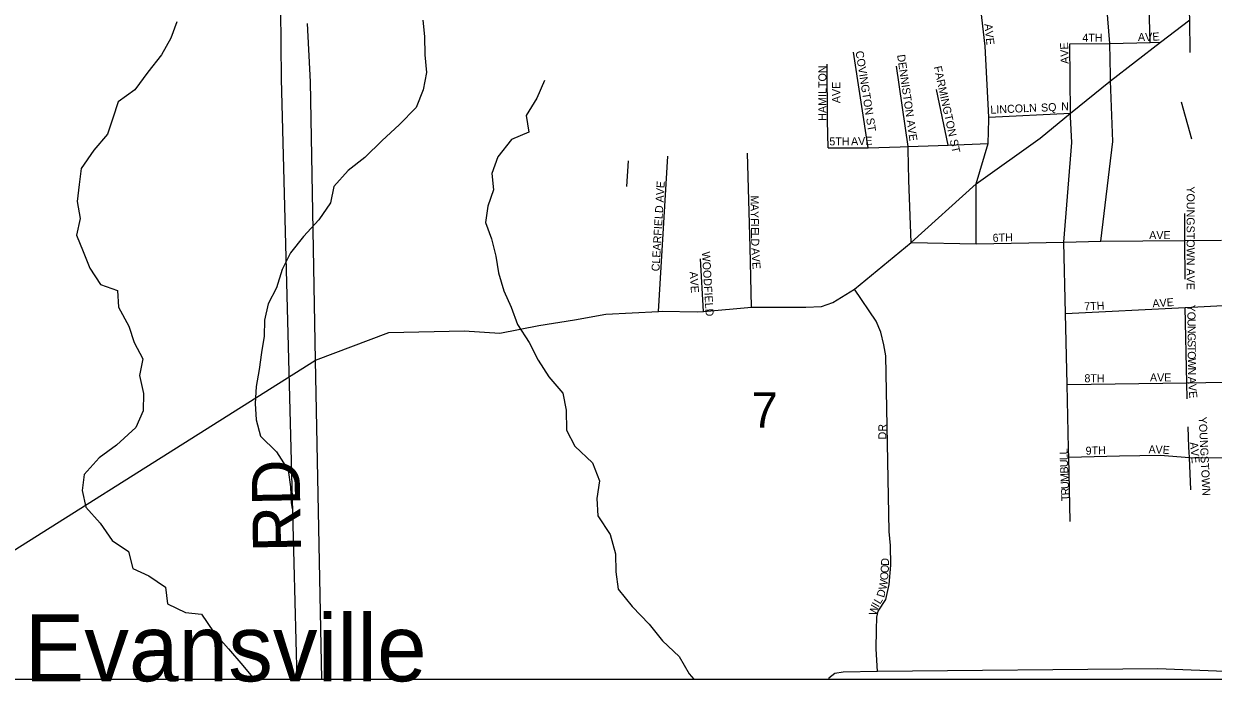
# Model space of a CAD drawing. Extents: x -37878.7 to -37844.7, y -19791.4 to -19769.4.
# Drawn here: x -37872.428 to -37871.021, y -19777.389 to -19776.611 of the extents above; entities that cross this region are included whole.
import ezdxf

# ---------------------------------------------------------------- set-up
doc = ezdxf.new("R2010")
doc.units = 0
for name, color, linetype in [('GM_X_County_Road', 7, 'Continuous'), ('GM_X_Minor_River', 7, 'Continuous'), ('GM_X_Section', 7, 'Continuous'), ('GM_X_Section_Text', 7, 'Continuous'), ('GM_X_Township_Road', 7, 'Continuous'), ('GM_X_Township_Road_Text', 7, 'Continuous'), ('GM_X_Township_Subdivision', 7, 'Continuous'), ('GM_X_Township_Subdivision_Text', 7, 'Continuous'), ('GM_X_Unincorporated_Text', 7, 'Continuous'), ('SH_Data', 7, 'Continuous')]:
    doc.layers.add(name, color=color, linetype=linetype)

msp = doc.modelspace()

# ---------------------------------------------------------------- linework, layer by layer
at = {"layer": 'GM_X_County_Road'}
for points in [[(-37872.0827, -19777.0084), (-37871.996, -19776.9759), (-37871.9068, -19776.974), (-37871.8646, -19776.9764), (-37871.8185, -19776.9676), (-37871.7765, -19776.9609), (-37871.7394, -19776.9542), (-37871.7083, -19776.9527), (-37871.6771, -19776.9509), (-37871.6726, -19776.9506), (-37871.6312, -19776.9515), (-37871.624, -19776.9511), (-37871.5669, -19776.9457), (-37871.5029, -19776.9457), (-37871.4842, -19776.9449), (-37871.471, -19776.9403), (-37871.4452, -19776.9247), (-37871.3781, -19776.8692), (-37871.3015, -19776.8), (-37871.2255, -19776.7462), (-37871.1899, -19776.7165), (-37871.1423, -19776.6783), (-37871.0832, -19776.6324), (-37871.0487, -19776.6062)], [(-37872.6858, -19777.3854), (-37872.5796, -19777.3214), (-37872.0827, -19777.0084)]]:
    msp.add_lwpolyline(points, dxfattribs=at)
at = {"layer": 'GM_X_Minor_River'}
for points in [[(-37872.2467, -19776.6084), (-37872.2539, -19776.6279), (-37872.2649, -19776.6475), (-37872.2811, -19776.668), (-37872.2966, -19776.6888), (-37872.3163, -19776.7033), (-37872.3224, -19776.7224), (-37872.3288, -19776.7415), (-37872.3451, -19776.7604), (-37872.3598, -19776.782), (-37872.3624, -19776.801), (-37872.3647, -19776.8208), (-37872.3612, -19776.8409), (-37872.3653, -19776.8607), (-37872.3574, -19776.8799), (-37872.3498, -19776.8998), (-37872.3369, -19776.9189), (-37872.317, -19776.9261), (-37872.3158, -19776.9458), (-37872.3036, -19776.9683), (-37872.2972, -19776.9875), (-37872.2869, -19777.007), (-37872.2911, -19777.0265), (-37872.2861, -19777.048), (-37872.2864, -19777.0685), (-37872.2951, -19777.0881), (-37872.3181, -19777.1091), (-37872.3387, -19777.1239), (-37872.3564, -19777.1437), (-37872.3587, -19777.1627), (-37872.3545, -19777.1823), (-37872.3374, -19777.2013), (-37872.3234, -19777.2215), (-37872.3038, -19777.2348), (-37872.2988, -19777.2548), (-37872.2797, -19777.2635), (-37872.2601, -19777.2767), (-37872.2578, -19777.2964), (-37872.2367, -19777.3066), (-37872.2174, -19777.3089), (-37872.2033, -19777.3298), (-37872.1855, -19777.3499), (-37872.1688, -19777.3693), (-37872.1553, -19777.3854)], [(-37871.9558, -19776.6064), (-37871.9539, -19776.6257), (-37871.9534, -19776.6477), (-37871.9515, -19776.6685), (-37871.9556, -19776.6891), (-37871.9635, -19776.7098), (-37871.9839, -19776.7303), (-37872.004, -19776.749), (-37872.0244, -19776.7688), (-37872.0442, -19776.7844), (-37872.0612, -19776.8033), (-37872.065, -19776.8224), (-37872.079, -19776.8424), (-37872.0971, -19776.8622), (-37872.1122, -19776.8815), (-37872.122, -19776.9014), (-37872.1288, -19776.9228), (-37872.1386, -19776.942), (-37872.1432, -19776.9611), (-37872.1435, -19776.9801), (-37872.1465, -19776.9995), (-37872.1495, -19777.0197), (-37872.1529, -19777.0395), (-37872.154, -19777.0596), (-37872.1528, -19777.079), (-37872.1479, -19777.0982), (-37872.1289, -19777.1168), (-37872.1152, -19777.1385), (-37872.1125, -19777.1582), (-37872.1114, -19777.1772), (-37872.1105, -19777.1843)], [(-37871.8119, -19776.6778), (-37871.8211, -19776.6986), (-37871.8337, -19776.7194), (-37871.8305, -19776.7388), (-37871.851, -19776.7478), (-37871.867, -19776.7683), (-37871.8743, -19776.788), (-37871.8722, -19776.807), (-37871.8791, -19776.8263), (-37871.8815, -19776.8457), (-37871.8744, -19776.8651), (-37871.8696, -19776.8856), (-37871.8663, -19776.9054), (-37871.86, -19776.9267), (-37871.8515, -19776.9457), (-37871.844, -19776.9663), (-37871.8301, -19776.9876), (-37871.8193, -19777.0085), (-37871.8069, -19777.0283), (-37871.7904, -19777.0474), (-37871.7863, -19777.0676), (-37871.7857, -19777.0911), (-37871.776, -19777.1101), (-37871.7553, -19777.13), (-37871.7467, -19777.1513), (-37871.7499, -19777.1722), (-37871.7489, -19777.1927), (-37871.7343, -19777.2144), (-37871.728, -19777.2376), (-37871.7274, -19777.2589), (-37871.7248, -19777.279), (-37871.7083, -19777.2996), (-37871.688, -19777.3206), (-37871.6722, -19777.3404), (-37871.6527, -19777.3587), (-37871.6407, -19777.3793), (-37871.6354, -19777.3854)]]:
    msp.add_lwpolyline(points, dxfattribs=at)
at = {"layer": 'GM_X_Section'}
msp.add_lwpolyline([(-37872.1046, -19777.3854), (-37872.1081, -19777.2484), (-37872.123, -19776.676), (-37872.1261, -19776.3478), (-37871.0074, -19776.3279), (-37870.9803, -19777.3854)], dxfattribs=at)
at = {"layer": 'GM_X_Township_Road'}
for points in [[(-37872.0751, -19777.3854), (-37872.0827, -19777.0084), (-37872.0885, -19776.6793), (-37872.0924, -19776.6107), (-37872.0924, -19776.6105)], [(-37870.9972, -19777.3771), (-37871.0863, -19777.3733), (-37871.4179, -19777.3765), (-37871.4585, -19777.3772), (-37871.4686, -19777.3788), (-37871.4756, -19777.3843), (-37871.4758, -19777.3854)]]:
    msp.add_lwpolyline(points, dxfattribs=at)
at = {"layer": 'GM_X_Township_Subdivision'}
for points in [[(-37871.1425, -19776.6721), (-37871.1434, -19776.634), (-37871.1591, -19776.4395)], [(-37871.0954, -19776.6331), (-37871.0987, -19776.5188), (-37871.1091, -19776.4656)], [(-37871.2865, -19776.7238), (-37871.2864, -19776.7212), (-37871.2906, -19776.6373), (-37871.3026, -19776.5353)], [(-37871.0484, -19776.6449), (-37871.0487, -19776.6062), (-37871.0494, -19776.5873)], [(-37871.1905, -19776.6345), (-37871.1434, -19776.634), (-37871.0954, -19776.6331), (-37871.0832, -19776.6324)], [(-37871.4291, -19776.7574), (-37871.4466, -19776.6443)], [(-37871.1897, -19776.7207), (-37871.1899, -19776.7165), (-37871.1905, -19776.6345)], [(-37871.4762, -19776.7573), (-37871.477, -19776.7252), (-37871.4776, -19776.6584)], [(-37871.3818, -19776.7596), (-37871.3819, -19776.7559), (-37871.3956, -19776.6609)], [(-37871.1396, -19776.7498), (-37871.1423, -19776.6783), (-37871.1425, -19776.6721)], [(-37871.3346, -19776.7545), (-37871.3483, -19776.6885)], [(-37871.0463, -19776.7473), (-37871.0584, -19776.7036)], [(-37871.2864, -19776.7212), (-37871.1899, -19776.7165)], [(-37871.3012, -19776.8711), (-37871.3015, -19776.8), (-37871.2871, -19776.7522), (-37871.2865, -19776.7238)], [(-37871.192, -19777.1131), (-37871.1937, -19777.0373), (-37871.1956, -19776.9533), (-37871.1975, -19776.8688), (-37871.1881, -19776.751), (-37871.1897, -19776.7207)], [(-37871.4762, -19776.7573), (-37871.4291, -19776.7574), (-37871.3913, -19776.7562)], [(-37871.3913, -19776.7562), (-37871.3819, -19776.7559), (-37871.3346, -19776.7545), (-37871.2871, -19776.7522)], [(-37871.3781, -19776.8692), (-37871.381, -19776.7956), (-37871.3818, -19776.7596)], [(-37871.1539, -19776.8678), (-37871.1396, -19776.7498)], [(-37871.7128, -19776.7728), (-37871.7149, -19776.803)], [(-37871.6771, -19776.9509), (-37871.666, -19776.7673)], [(-37871.5669, -19776.9457), (-37871.5688, -19776.8751), (-37871.5719, -19776.7639)], [(-37871.0543, -19776.9128), (-37871.0544, -19776.8671), (-37871.0544, -19776.8352)], [(-37871.3781, -19776.8692), (-37871.3012, -19776.8711), (-37871.1975, -19776.8688), (-37871.1539, -19776.8678), (-37871.0544, -19776.8671), (-37871.0112, -19776.8668)], [(-37871.624, -19776.9511), (-37871.6274, -19776.8886)], [(-37871.4179, -19777.3765), (-37871.4195, -19777.3499), (-37871.4191, -19777.3273), (-37871.4187, -19777.3121), (-37871.4171, -19777.3051), (-37871.4081, -19777.2914), (-37871.4042, -19777.2738), (-37871.4023, -19777.2508), (-37871.4027, -19777.2274), (-37871.4042, -19777.211), (-37871.4081, -19777.0035), (-37871.4105, -19776.9902), (-37871.414, -19776.9754), (-37871.4195, -19776.9625), (-37871.4452, -19776.9247)], [(-37871.1956, -19776.9533), (-37871.0543, -19776.9462), (-37871.0093, -19776.944)], [(-37871.0516, -19777.0542), (-37871.0521, -19777.0351), (-37871.0543, -19776.9462)], [(-37871.1937, -19777.0373), (-37871.0521, -19777.0351), (-37871.0071, -19777.0345)], [(-37871.0497, -19777.1115), (-37871.0508, -19777.0873)], [(-37871.0474, -19777.1618), (-37871.0492, -19777.1237), (-37871.0495, -19777.1171), (-37871.0497, -19777.1115)], [(-37871.1901, -19777.1993), (-37871.1918, -19777.1232), (-37871.192, -19777.1137), (-37871.192, -19777.1131)], [(-37871.1918, -19777.1232), (-37871.1317, -19777.1216), (-37871.0838, -19777.1207), (-37871.0492, -19777.1237), (-37871.0045, -19777.1238)]]:
    msp.add_lwpolyline(points, dxfattribs=at)
at = {"layer": 'SH_Data'}
msp.add_line((-37876.1504, -19777.3854), (-37869.1504, -19777.3854), dxfattribs=at)

# ---------------------------------------------------------------- texts
at = {"layer": 'GM_X_Section_Text'}
msp.add_text('7', height=0.0419, rotation=0, dxfattribs=at).set_placement((-37871.5671, -19777.0883))
at = {"layer": 'GM_X_Township_Road_Text'}
msp.add_text('RD', height=0.05682, rotation=90.9872, dxfattribs=at).set_placement((-37872.0998, -19777.2351))
at = {"layer": 'GM_X_Township_Subdivision_Text'}
for s, rotation, p in [('AVE', 275.9101, (-37871.2916, -19776.6112)), ('AVE', 92.0442, (-37871.1918, -19776.6581)), ('4TH', 0, (-37871.1758, -19776.6321)), ('A', 0.0984, (-37871.11, -19776.6312)), ('V', 1.6154, (-37871.1014, -19776.6312)), ('E', 4.1934, (-37871.0926, -19776.631)), ('COVINGTON ST', 279.0011, (-37871.4441, -19776.6436)), ('DENNISTON AVE', 278.2772, (-37871.3949, -19776.6478)), ('HAMILTON', 90, (-37871.4785, -19776.7255)), ('FARMINGTON ST', 282.3071, (-37871.3516, -19776.6618)), ('AVE', 90, (-37871.4622, -19776.7047)), ('N', 0, (-37871.2008, -19776.7132)), ('LINCOLN', 2.8158, (-37871.2843, -19776.7173)), ('SQ', 3.1778, (-37871.2244, -19776.7148)), ('5TH', 0, (-37871.475, -19776.7546)), ('AVE', 1.9774, (-37871.4492, -19776.7546)), ('CLEARFIELD AVE', 86.5761, (-37871.676, -19776.9037)), ('M', 270.7832, (-37871.5682, -19776.8138)), ('YOUNGSTOWN AVE', 270, (-37871.0524, -19776.803)), ('A', 270.7983, (-37871.5681, -19776.8238)), ('Y', 270.7869, (-37871.568, -19776.8322)), ('F', 270.7799, (-37871.5679, -19776.8405)), ('I', 270.7869, (-37871.5678, -19776.8472)), ('E', 270.7799, (-37871.5677, -19776.8513)), ('L', 270.7923, (-37871.5676, -19776.858)), ('6TH', 2.2892, (-37871.2817, -19776.8687)), ('AVE', 0, (-37871.0967, -19776.8654)), ('D', 270.9054, (-37871.5675, -19776.8647)), ('WOODFIELD', 273.4455, (-37871.6257, -19776.8804)), ('A', 273.3422, (-37871.5673, -19776.8759)), ('V', 273.812, (-37871.5668, -19776.8843)), ('E', 273.8117, (-37871.5662, -19776.8927)), ('AVE', 273.9429, (-37871.6403, -19776.904)), ('7TH', 2.2892, (-37871.1734, -19776.9496)), ('AVE', 3.9469, (-37871.0926, -19776.9462)), ('Y', 270.5245, (-37871.0516, -19776.943)), ('O', 270.5245, (-37871.0515, -19776.9513)), ('U', 270.5245, (-37871.0514, -19776.9597)), ('N', 270.5337, (-37871.0513, -19776.968)), ('G', 270.5245, (-37871.0512, -19776.9763)), ('S', 270.5191, (-37871.0512, -19776.9847)), ('O', 270.5337, (-37871.0511, -19776.998)), ('T', 270.5168, (-37871.0511, -19776.9913)), ('W', 270.5212, (-37871.051, -19777.0063)), ('8TH', 0, (-37871.1733, -19777.0346)), ('AVE', 0, (-37871.0958, -19777.0337)), ('N', 270.522, (-37871.0509, -19777.0172)), ('A', 271.6775, (-37871.0508, -19777.0282)), ('V', 274.9433, (-37871.0505, -19777.0371)), ('E', 275.4388, (-37871.0498, -19777.0455)), ('YOUNGSTOWN', 272.8055, (-37871.0382, -19777.0756)), ('DR', 90, (-37871.4076, -19777.1022)), ('9TH', 2.2892, (-37871.1717, -19777.1204)), ('A', 359.9016, (-37871.0975, -19777.1187)), ('V', 358.262, (-37871.0893, -19777.1187)), ('E', 355.8035, (-37871.081, -19777.119)), ('AVE', 275.5225, (-37871.0486, -19777.1057)), ('L', 91.9947, (-37871.1932, -19777.1198)), ('L', 92.3228, (-37871.1929, -19777.1265)), ('U', 92.3338, (-37871.1926, -19777.1348)), ('B', 92.3319, (-37871.1923, -19777.1423)), ('M', 92.3321, (-37871.1919, -19777.1523)), ('U', 92.3338, (-37871.1915, -19777.1606)), ('R', 92.329, (-37871.1912, -19777.1681)), ('T', 92.3228, (-37871.191, -19777.1748)), ('O', 86.294, (-37871.405, -19777.2604)), ('D', 88.9343, (-37871.4045, -19777.2516)), ('O', 86.0123, (-37871.4056, -19777.2688)), ('D', 72.2697, (-37871.4105, -19777.2898)), ('W', 80.0837, (-37871.4076, -19777.2805)), ('I', 60.3256, (-37871.4169, -19777.3013)), ('L', 59.0011, (-37871.4149, -19777.2977)), ('W', 75.5397, (-37871.4194, -19777.3111))]:
    msp.add_text(s, height=0.00947, rotation=rotation, dxfattribs=at).set_placement(p)
at = {"layer": 'GM_X_Unincorporated_Text'}
msp.add_text('Evansville', height=0.07898, rotation=0, dxfattribs=at).set_placement((-37872.4267, -19777.3881))

doc.saveas('drawing.dxf')
